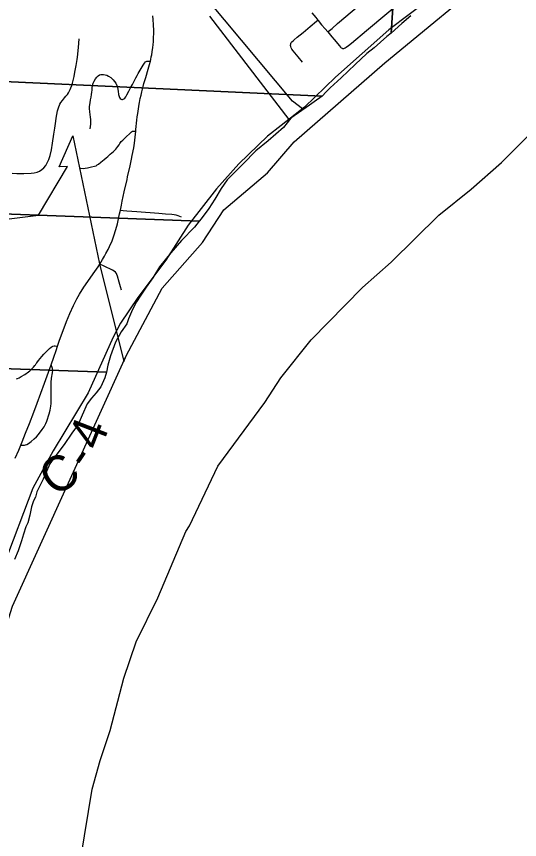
# Model space of a CAD drawing. Extents: x 21.4 to 65.3, y 4 to 26.
# Drawn here: x 26.947 to 27.755, y 22.248 to 23.571 of the extents above; entities that cross this region are included whole.
import ezdxf

# ---------------------------------------------------------------- set-up
doc = ezdxf.new("R2010")
doc.units = 0
for name, color, linetype in [('Default', 7, 'Continuous'), ('GM_X_City_Street', 7, 'Continuous'), ('GM_X_County_Road', 7, 'Continuous'), ('GM_X_County_Road_Text', 7, 'Continuous'), ('GM_X_Major_River', 7, 'Continuous'), ('GM_X_Minor_River', 7, 'Continuous'), ('GM_X_Section', 7, 'Continuous'), ('GM_X_State_Route', 7, 'Continuous'), ('GM_X_Township_Road', 7, 'Continuous'), ('SH_Cut_Line', 7, 'Continuous')]:
    doc.layers.add(name, color=color, linetype=linetype)

msp = doc.modelspace()

# ---------------------------------------------------------------- linework, layer by layer
at = {"layer": 'Default'}
for points in [[(26.8806, 21.8662), (26.8662, 22.382), (26.8983, 22.4902), (26.9403, 22.6234), (27.1232, 23.0257), (27.1807, 23.1342), (27.2457, 23.2074), (27.2797, 23.2602), (27.35, 23.3198), (27.3927, 23.3695), (27.5383, 23.4966), (27.7231, 23.6491), (27.7926, 23.7076), (27.9329, 23.8039), (28.1831, 23.9937), (28.2398, 24.0415), (28.3384, 24.1861), (28.4624, 24.3121), (28.5577, 24.377), (28.648, 24.4047), (28.7897, 24.4217), (28.9262, 24.4567), (29.0418, 24.4692)], [(26.8869, 23.24), (26.9821, 23.2516), (27.0291, 23.3297), (27.0153, 23.3292), (27.0375, 23.379), (27.0805, 23.1731), (27.1191, 23.0165), (27.1232, 23.0257), (27.1807, 23.1342), (27.2457, 23.2074), (27.2797, 23.2602), (27.35, 23.3198), (27.3927, 23.3695), (27.5383, 23.4966), (27.7231, 23.6491)]]:
    msp.add_lwpolyline(points, dxfattribs=at)
at = {"layer": 'GM_X_City_Street'}
for points in [[(27.4467, 23.5461), (27.4476, 23.5468), (27.4537, 23.5518), (27.4627, 23.5594), (27.4858, 23.5794), (27.4983, 23.5895), (27.5041, 23.5942), (27.5145, 23.6029), (27.5256, 23.612), (27.5333, 23.6184), (27.5469, 23.6299), (27.5537, 23.6358), (27.5544, 23.6363)], [(27.4064, 23.4977), (27.3992, 23.506), (27.3912, 23.5157), (27.3893, 23.5183), (27.3881, 23.5206), (27.3875, 23.5224), (27.3872, 23.5243), (27.3872, 23.5254), (27.3873, 23.5265), (27.3876, 23.5277), (27.3883, 23.5291), (27.3892, 23.5301), (27.391, 23.5319), (27.3928, 23.5334), (27.3977, 23.5374), (27.4071, 23.5452), (27.4183, 23.5546), (27.4289, 23.5636), (27.4307, 23.5652)], [(26.94, 23.3189), (26.9474, 23.3187), (26.9586, 23.3185), (26.9704, 23.3189), (26.9753, 23.3194), (26.9801, 23.3206), (26.984, 23.3224), (26.9876, 23.3248), (26.9908, 23.3277), (26.9939, 23.3316), (26.9964, 23.3358), (26.9987, 23.3409), (27.0008, 23.3473), (27.003, 23.3564), (27.005, 23.3674), (27.0068, 23.3816), (27.0083, 23.3913), (27.01, 23.4025), (27.0107, 23.4077), (27.0115, 23.4136), (27.0128, 23.419), (27.0142, 23.4242), (27.0164, 23.4298), (27.0184, 23.4326), (27.0207, 23.4359), (27.0243, 23.4404), (27.0263, 23.4428), (27.0288, 23.4456), (27.0303, 23.4481), (27.0317, 23.4504), (27.0331, 23.4535), (27.0343, 23.456), (27.0356, 23.4602), (27.0368, 23.4637), (27.0393, 23.4745), (27.0407, 23.4812), (27.0426, 23.4922), (27.0443, 23.502), (27.0448, 23.5057), (27.0466, 23.521), (27.0471, 23.5279), (27.0474, 23.5347)], [(27.0651, 23.3902), (27.0656, 23.394), (27.0661, 23.398), (27.0663, 23.4016), (27.0663, 23.4049), (27.066, 23.4097), (27.0654, 23.4127), (27.0646, 23.4182), (27.0643, 23.4226), (27.0644, 23.4263), (27.065, 23.4322), (27.0658, 23.4369), (27.0666, 23.441), (27.0674, 23.4456), (27.068, 23.4492), (27.0683, 23.4526), (27.0686, 23.4556), (27.0692, 23.46), (27.0702, 23.4635), (27.0716, 23.467), (27.0739, 23.4707), (27.0762, 23.4736), (27.078, 23.4753), (27.0803, 23.4769), (27.0823, 23.4776), (27.084, 23.4778), (27.0865, 23.4777), (27.0895, 23.4771), (27.0919, 23.4764), (27.0947, 23.475), (27.0984, 23.4727), (27.1002, 23.4712), (27.1024, 23.469), (27.1044, 23.4666), (27.1064, 23.4635), (27.1079, 23.4601), (27.1089, 23.4566), (27.1101, 23.4511), (27.111, 23.4456), (27.1118, 23.4425), (27.1125, 23.4408), (27.1135, 23.4393), (27.1149, 23.4381), (27.1161, 23.4377), (27.1172, 23.4376), (27.1184, 23.4378), (27.1195, 23.4383), (27.121, 23.4395), (27.1225, 23.4415), (27.1244, 23.4451), (27.1274, 23.4511), (27.1305, 23.4571), (27.133, 23.4618), (27.1348, 23.465), (27.1386, 23.4721), (27.1408, 23.4762), (27.1425, 23.4794), (27.1471, 23.4872), (27.1503, 23.4924), (27.1527, 23.496), (27.1543, 23.4978), (27.1562, 23.499), (27.1581, 23.4992), (27.1597, 23.4992), (27.1619, 23.499)], [(27.0497, 23.3269), (27.0538, 23.3268), (27.0572, 23.327), (27.0609, 23.3276), (27.0676, 23.329), (27.0721, 23.3301), (27.0747, 23.331), (27.0766, 23.3322), (27.0788, 23.3337), (27.0825, 23.3369), (27.0878, 23.3412), (27.0907, 23.3435), (27.0935, 23.3458), (27.0944, 23.3466), (27.0976, 23.3495), (27.1026, 23.3537), (27.1049, 23.3559), (27.1065, 23.3578), (27.1096, 23.3618), (27.1117, 23.3647), (27.1131, 23.3668), (27.1151, 23.3697), (27.1176, 23.3723), (27.1202, 23.3747), (27.1316, 23.3853), (27.1332, 23.3864), (27.1345, 23.3868), (27.1366, 23.3868), (27.1385, 23.3868)], [(27.1138, 23.2597), (27.1183, 23.2591), (27.1244, 23.2584), (27.1403, 23.2574), (27.1755, 23.2547), (27.1864, 23.2539), (27.1962, 23.2529), (27.1999, 23.2525), (27.2028, 23.2519), (27.2062, 23.2509), (27.2116, 23.2491)], [(27.1154, 23.131), (27.1141, 23.1364), (27.1119, 23.144), (27.1092, 23.1537), (27.1083, 23.1562), (27.1074, 23.1578), (27.1059, 23.1597), (27.1036, 23.1618), (27.101, 23.1634), (27.0876, 23.1694), (27.0807, 23.1726)]]:
    msp.add_lwpolyline(points, dxfattribs=at)
at = {"layer": 'GM_X_County_Road'}
for points in [[(27.471, 23.5192), (27.4717, 23.5192), (27.4724, 23.5193), (27.4737, 23.5199), (27.475, 23.5205), (27.4765, 23.5214), (27.4803, 23.5242), (27.4848, 23.5279), (27.5092, 23.5482), (27.5417, 23.5757), (27.5615, 23.5923), (27.5792, 23.6074), (27.5941, 23.6199), (27.6108, 23.6338), (27.6297, 23.65), (27.6388, 23.6573), (27.6581, 23.6736), (27.6918, 23.7015)], [(27.421, 23.5767), (27.4275, 23.5691), (27.4307, 23.5652), (27.4315, 23.5642), (27.4369, 23.5576), (27.4425, 23.5511), (27.4467, 23.5461), (27.4532, 23.5384), (27.4569, 23.5339), (27.4654, 23.5237), (27.4674, 23.5217), (27.4686, 23.5205), (27.4697, 23.5197), (27.4703, 23.5194), (27.471, 23.5192)], [(26.9538, 22.8818), (26.9574, 22.8819), (26.9597, 22.8821), (26.9612, 22.8824), (26.9635, 22.8832), (26.9662, 22.8848), (26.9707, 22.888), (26.9755, 22.892), (26.979, 22.8954), (26.9823, 22.8992), (26.9884, 22.9069), (26.9912, 22.9111), (26.994, 22.9166), (26.9957, 22.9206), (26.9995, 22.9324), (27.001, 22.9384), (27.002, 22.9445), (27.0024, 22.9488), (27.0025, 22.9544), (27.0025, 22.9606), (27.0024, 22.9772), (27.0026, 22.9803), (27.0028, 22.9828), (27.0034, 22.9895), (27.0047, 22.9982), (27.0052, 23.0027), (27.0048, 23.0051), (27.0026, 23.011)]]:
    msp.add_lwpolyline(points, dxfattribs=at)
at = {"layer": 'GM_X_Major_River'}
msp.add_line((27.4094, 23.4251), (27.3721, 23.3957), dxfattribs=at)
for points in [[(27.6426, 23.6238), (27.545, 23.5494), (27.4595, 23.4735), (27.4094, 23.4251)], [(27.0502, 22.2179), (27.0687, 22.3289), (27.0813, 22.3752), (27.0974, 22.4235), (27.1194, 22.5075), (27.1392, 22.5657), (27.1737, 22.6364), (27.219, 22.7429), (27.225, 22.7524), (27.2703, 22.8479), (27.3455, 22.9507), (27.3715, 22.9899), (27.4204, 23.0512), (27.5028, 23.1351), (27.5488, 23.1762), (27.6252, 23.2517), (27.6772, 23.2933), (27.7258, 23.3364), (27.783, 23.3936), (27.8504, 23.4519), (27.9767, 23.553), (28.0317, 23.606)], [(27.3721, 23.3957), (27.3499, 23.3785), (27.3039, 23.3339), (27.2682, 23.2939), (27.2227, 23.2357), (27.187, 23.179), (27.1419, 23.1192), (27.1141, 23.0781), (27.1024, 23.0556), (27.062, 22.9659), (27.006, 22.873), (26.973, 22.8129), (26.9266, 22.6893), (26.8772, 22.5703), (26.8597, 22.503), (26.8575, 22.4909), (26.8322, 22.3833), (26.828, 22.3063), (26.8227, 22.1096)]]:
    msp.add_lwpolyline(points, dxfattribs=at)
at = {"layer": 'GM_X_Minor_River'}
msp.add_line((27.3842, 23.4055), (27.4061, 23.4226), dxfattribs=at)
for points in [[(27.4061, 23.4226), (27.3901, 23.4346), (27.2539, 23.5988)], [(27.2569, 23.5715), (27.3842, 23.4055)]]:
    msp.add_lwpolyline(points, dxfattribs=at)
at = {"layer": 'GM_X_Section'}
for points in [[(26.5825, 24.5101), (27.6091, 24.4648), (27.5486, 23.5443), (27.5415, 23.5386), (27.5313, 23.5298), (27.5214, 23.5207), (27.5097, 23.5112), (27.4908, 23.4937), (27.4682, 23.4724), (27.4508, 23.456), (27.444, 23.4496), (27.4376, 23.4427), (26.5198, 23.4854)], [(26.5198, 23.4854), (27.4376, 23.4427), (27.4251, 23.4336), (27.4176, 23.4283), (27.3873, 23.4073), (27.3756, 23.3925), (27.3511, 23.3712), (27.3311, 23.3548), (27.311, 23.3339), (27.2963, 23.3195), (27.285, 23.3081), (27.2756, 23.2944), (27.2654, 23.2773), (27.256, 23.2621), (27.2435, 23.2454), (27.2404, 23.2418), (26.5078, 23.2694)], [(27.2404, 23.2418), (27.2326, 23.2325), (27.2118, 23.2108), (27.1948, 23.1911), (27.1767, 23.1683), (27.1658, 23.1508), (27.1552, 23.1356), (27.1466, 23.1231), (27.1394, 23.1121), (27.133, 23.0999), (27.1266, 23.0851), (27.124, 23.0768), (27.1153, 23.0642), (27.1059, 23.0475), (27.098, 23.0255), (27.0935, 23.0107), (27.0913, 22.9992), (26.4931, 23.0203), (26.5078, 23.2694)]]:
    msp.add_lwpolyline(points, close=True, dxfattribs=at)
for points in [[(27.58, 23.5721), (27.5656, 23.5595), (27.5486, 23.5443), (27.6091, 24.4648)], [(26.4931, 23.0203), (27.0913, 22.9992), (27.0887, 22.9899), (27.0823, 22.9755), (27.0748, 22.966), (27.0676, 22.9576), (27.0604, 22.9481), (27.0525, 22.9303), (27.0458, 22.9151), (27.0356, 22.901), (27.0235, 22.8828), (27.0099, 22.8653), (27.0005, 22.852), (26.9896, 22.8274), (26.9798, 22.8069), (26.9772, 22.7982), (26.9742, 22.7925), (26.9712, 22.783), (26.9682, 22.7693), (26.9652, 22.7572), (26.9618, 22.7504), (26.9581, 22.739), (26.9551, 22.728), (26.9498, 22.7121), (26.9438, 22.698)]]:
    msp.add_lwpolyline(points, dxfattribs=at)
at = {"layer": 'GM_X_State_Route'}
for points in [[(27.0807, 23.1726), (27.0852, 23.1801), (27.0884, 23.1858), (27.0906, 23.1898), (27.094, 23.1963), (27.0964, 23.2014), (27.1004, 23.2105), (27.1035, 23.2186), (27.1067, 23.2286), (27.109, 23.2375), (27.1125, 23.2538), (27.1138, 23.2597), (27.1154, 23.2678), (27.1167, 23.2738), (27.1201, 23.289), (27.1245, 23.3089), (27.1254, 23.3131), (27.1295, 23.3311), (27.1316, 23.3414), (27.1328, 23.3473), (27.1352, 23.36), (27.1363, 23.3673), (27.138, 23.3815), (27.1385, 23.3868), (27.1387, 23.3895), (27.1402, 23.4041), (27.1409, 23.4096), (27.1416, 23.4152), (27.1421, 23.4188), (27.1427, 23.4224), (27.144, 23.4297), (27.1445, 23.4327), (27.1458, 23.4388), (27.147, 23.4442), (27.1482, 23.4496), (27.1492, 23.4539), (27.1504, 23.4585), (27.1517, 23.4632), (27.1544, 23.4728), (27.1585, 23.4864), (27.1606, 23.4936), (27.1619, 23.499), (27.1627, 23.502), (27.1634, 23.506), (27.1641, 23.5092), (27.1649, 23.5141), (27.1659, 23.5208), (27.1664, 23.5255), (27.1669, 23.5309), (27.1672, 23.5377), (27.1673, 23.5428), (27.1673, 23.5484), (27.167, 23.5575), (27.1665, 23.5659), (27.1661, 23.5721)], [(27.07, 23.1573), (27.0779, 23.1686), (27.0807, 23.1726)], [(26.9449, 22.861), (26.9507, 22.8741), (26.9538, 22.8818), (26.9561, 22.8873), (26.9615, 22.9012), (26.9677, 22.9168), (26.9748, 22.9347), (26.9801, 22.9492), (26.986, 22.9656), (26.9917, 22.9814), (27.0005, 23.0053), (27.0026, 23.011), (27.007, 23.0234), (27.0106, 23.034), (27.0129, 23.0408), (27.0162, 23.0504), (27.0218, 23.0662), (27.0272, 23.0808), (27.0326, 23.0934), (27.0386, 23.1064), (27.044, 23.117), (27.0483, 23.1246), (27.0553, 23.1357), (27.0689, 23.1556), (27.07, 23.1573)]]:
    msp.add_lwpolyline(points, dxfattribs=at)
at = {"layer": 'GM_X_Township_Road'}
msp.add_lwpolyline([(26.9467, 22.9886), (26.9485, 22.989), (26.9513, 22.9902), (26.9547, 22.992), (26.9603, 22.9957), (26.966, 22.9999), (26.9681, 23.0014), (26.9699, 23.003), (26.9717, 23.0046), (26.9725, 23.0054), (26.9741, 23.0071), (26.9763, 23.0098), (26.9773, 23.0112), (26.9786, 23.013), (26.9796, 23.0143), (26.9823, 23.018), (26.9874, 23.0242), (26.9907, 23.0279), (26.9919, 23.0292), (26.9966, 23.0339), (27, 23.037), (27.0025, 23.0393), (27.004, 23.0403), (27.0054, 23.041), (27.0073, 23.0415), (27.0092, 23.0415), (27.0129, 23.0408)], dxfattribs=at)
at = {"layer": 'SH_Cut_Line'}
msp.add_lwpolyline([(26.8806, 21.8662), (26.8662, 22.382), (26.8983, 22.4902), (26.9403, 22.6234), (27.1232, 23.0257), (27.1807, 23.1342), (27.2457, 23.2074), (27.2797, 23.2602), (27.35, 23.3198), (27.3927, 23.3695), (27.5383, 23.4966), (27.7231, 23.6491), (27.7926, 23.7076), (27.9329, 23.8039), (28.1831, 23.9937), (28.2398, 24.0415), (28.3384, 24.1861), (28.4624, 24.3121), (28.5577, 24.377), (28.648, 24.4047), (28.7897, 24.4217), (28.9262, 24.4567), (29.0418, 24.4692)], dxfattribs=at)

# ---------------------------------------------------------------- texts
at = {"layer": 'GM_X_County_Road_Text'}
for s, rotation, p in [('4', 68.6685, (27.0811, 22.8713)), ('C', 37.3937, (27.0107, 22.7969)), ('-', 55.695, (27.0614, 22.8396))]:
    msp.add_text(s, height=0.0568, rotation=rotation, dxfattribs=at).set_placement(p)

doc.saveas('drawing.dxf')
